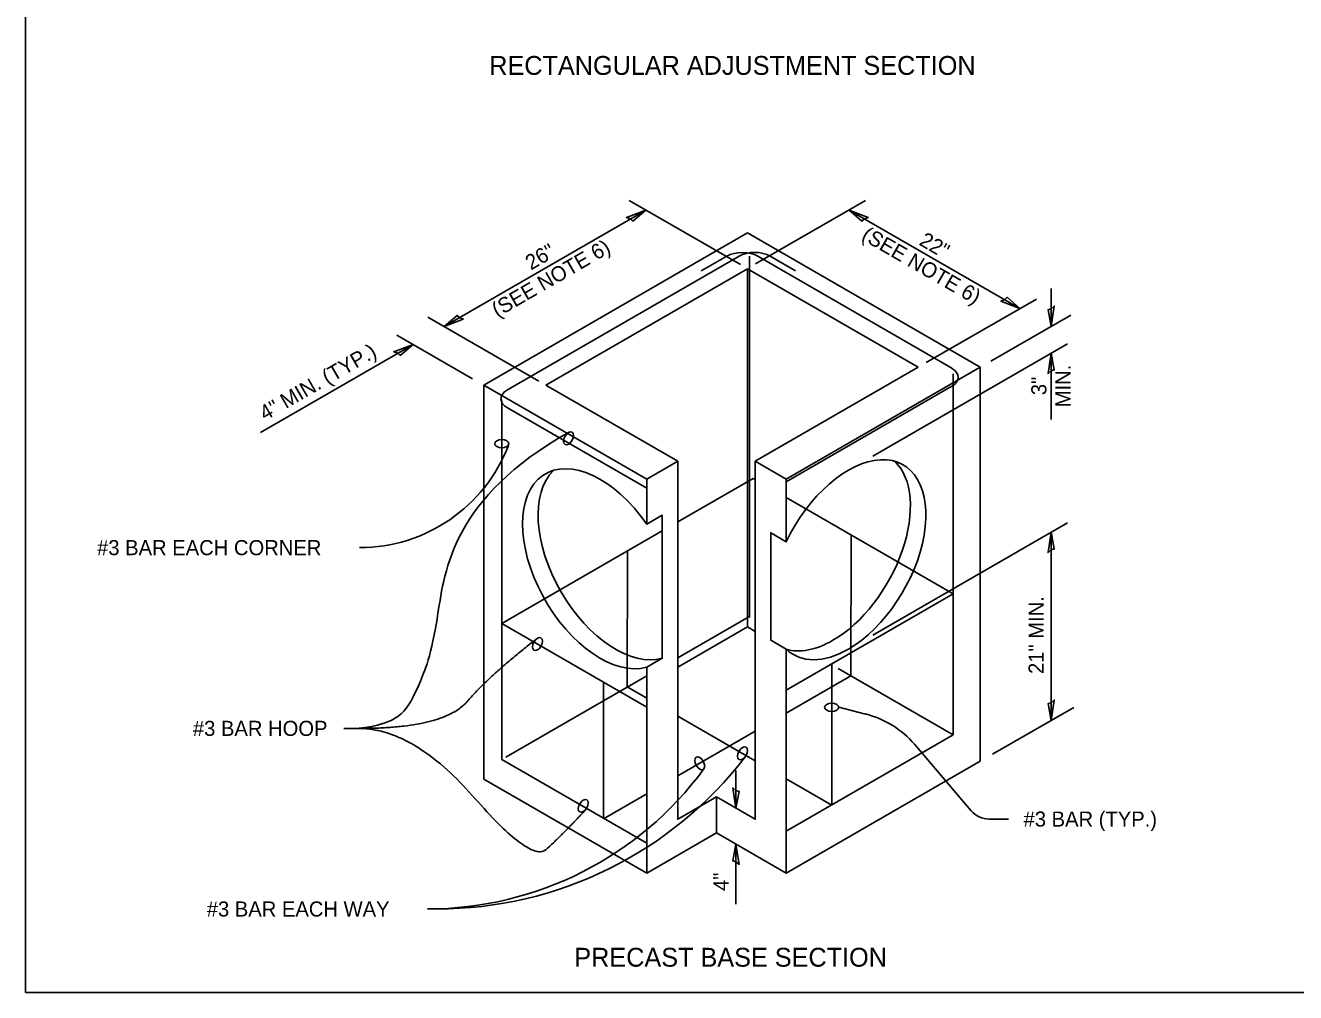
# Model space of a CAD drawing. Extents: x 99862 to 103151, y 100000 to 102076.
# Drawn here: x 99862 to 101209, y 100000 to 101025 of the extents above; entities that cross this region are included whole.
import ezdxf

# ---------------------------------------------------------------- set-up
doc = ezdxf.new("R2010")
doc.units = 0
for name, color, linetype in [('Level 1', 7, 'Continuous'), ('Level 15', 7, 'Continuous'), ('Level 20', 7, 'Continuous'), ('Level 34', 7, 'Continuous'), ('Level 44', 7, 'Continuous'), ('Level 60', 7, 'Continuous'), ('Level 8', 7, 'Continuous')]:
    doc.layers.add(name, color=color, linetype=linetype)

msp = doc.modelspace()

# ---------------------------------------------------------------- linework, layer by layer
at = {"layer": 'Level 1'}
for p, q in [((100348, 100643.8), (100627.6, 100805.3)), ((100627.6, 100805.3), (100874.4, 100662.8)), ((100627.6, 100767.3), (100413.8, 100643.8)), ((100808.5, 100662.8), (100627.6, 100767.3)), ((100627.6, 100767.3), (100627.6, 100387.4)), ((100635.8, 100563.1), (100808.5, 100662.8)), ((100874.4, 100662.8), (100668.7, 100544.1)), ((100874.4, 100662.8), (100874.4, 100244.9)), ((100520.7, 100544.1), (100347.9, 100643.8)), ((100348, 100643.8), (100348, 100225.9)), ((100413.8, 100643.8), (100553.6, 100563.1)), ((100553.6, 100344.6), (100627.6, 100387.4)), ((100635.8, 100382.6), (100627.6, 100387.4)), ((100668.7, 100126.2), (100874.4, 100244.9)), ((100348, 100225.9), (100520.7, 100126.2))]:
    msp.add_line(p, q, dxfattribs=at)
msp.add_lwpolyline([(99862, 99999.5), (103151, 99999.5), (103151, 102075.5), (99862, 102075.5)], close=True, dxfattribs=at)
for centre, major_axis, start_param, end_param in [((100471.3, 100449.1), (-58.1, 100.7), 4.853387, 9.28378), ((100734.5, 100458.7), (58.1, 100.7), 3.926991, 7.995826), ((100718.1, 100468.1), (58.1, 100.7), 3.926991, 6.141613), ((100487.8, 100458.6), (-58.1, 100.7), 0.144003, 3.001512), ((100718.1, 100468.1), (58.1, 100.7), 3.282336, 3.926991), ((100734.5, 100458.7), (58.1, 100.7), 2.999618, 3.926991)]:
    msp.add_ellipse(centre, major_axis=major_axis, ratio=0.57735, start_param=start_param, end_param=end_param, dxfattribs=at)
at = {"layer": 'Level 15'}
for p, q in [((100305.9, 100706.1), (100519.7, 100829.6)), ((100620.1, 100771.7), (100502.2, 100839.6)), ((100636.2, 100772.4), (100752.6, 100839.6)), ((100916.5, 100725.2), (100735.3, 100829.6)), ((100817.2, 100667.8), (100933.9, 100735.2)), ((100949.6, 100706.2), (100949.6, 100746.2)), ((100406.4, 100648.1), (100288.6, 100716)), ((100885.7, 100669.4), (100970.5, 100718.2)), ((100336, 100650.7), (100255.7, 100697)), ((100111.2, 100593.5), (100273, 100687.1)), ((100966.9, 100687.7), (100760.5, 100568.6)), ((100949.6, 100607.3), (100949.6, 100677.7)), ((100966.9, 100497.8), (100760.5, 100378.7)), ((100949.6, 100487.8), (100949.6, 100288.2)), ((100724.4, 100302.1), (100752.6, 100295)), ((100887.4, 100252.3), (100973.5, 100302)), ((100199.5, 100279.8), (100215.5, 100279.8)), ((100864.8, 100192.4), (100804.6, 100262.9)), ((100615.3, 100195.1), (100615.3, 100235.1)), ((100888.3, 100183.6), (100883.8, 100183.6)), ((100888.3, 100183.6), (100904.3, 100183.6)), ((100615.3, 100093.4), (100615.3, 100157)), ((100290.4, 100088.2), (100306.4, 100088.2))]:
    msp.add_line(p, q, dxfattribs=at)
for centre, radius, start, end in [((100216.2, 100640.9), 169.4, 270, 338.8329), ((100728.5, 100198), 100, 40.4774, 76.0603), ((100298.2, 100500), 411.8, 270, 322.5447), ((100288.2, 100451.6), 363.4, 270, 323.7669), ((100883.8, 100208.6), 25, 220.4774, 270)]:
    msp.add_arc(centre, radius, start, end, dxfattribs=at)
for centre, major_axis in [((100437.9, 100587.5), (3.75, 6.5)), ((100367.1, 100581.7), (-7.5, 0)), ((100404.9, 100369.2), (3.75, 6.5)), ((100716.9, 100302.1), (-7.5, 0)), ((100576.9, 100242.8), (-3.75, 6.5)), ((100622.3, 100253.2), (3.75, 6.5)), ((100453.5, 100197.6), (3.75, 6.5))]:
    msp.add_ellipse(centre, major_axis=major_axis, ratio=0.57735, dxfattribs=at)
for points, degree in [([(100438.6, 100594.1), (100314.7, 100524.3), (100298.7, 100370.8), (100279, 100325.8), (100263.6, 100290.9), (100228.2, 100281), (100215.8, 100279.9), (100215.6, 100279.9), (100215.4, 100279.8)], 3), ([(100215.5, 100279.8), (100305.5, 100279.5), (100355, 100336.8), (100403.6, 100374.4)], 2), ([(100215.5, 100279.8), (100274.2, 100279.1), (100398.3, 100136.8), (100430.2, 100165.9), (100456, 100193.5)], 2)]:
    msp.add_open_spline(points, degree=degree, dxfattribs=at)
at = {"layer": 'Level 34'}
for p, q in [((100605.7, 100780.6), (100578.6, 100765)), ((100629.8, 100397.5), (100629.8, 100780.7)), ((100651.5, 100780.7), (100678.6, 100765)), ((100845.7, 100272.9), (100845.7, 100656)), ((100668.7, 100541.3), (100844.4, 100642.8)), ((100367.1, 100246.8), (100367.1, 100627.6)), ((100520.7, 100534.5), (100373.1, 100619.7)), ((100553.6, 100498.8), (100633.5, 100545)), ((100633.5, 100545), (100635.8, 100543.6)), ((100668.7, 100524.6), (100845.7, 100422.4)), ((100367.1, 100391.1), (100537.2, 100489.4)), ((100737.3, 100335.5), (100737.5, 100484.9)), ((100500.1, 100323.7), (100500.2, 100468)), ((100845.7, 100422.4), (100668.7, 100320.2)), ((100553.6, 100354.5), (100628.9, 100398.1)), ((100520.7, 100302.3), (100367.1, 100391.1)), ((100716.9, 100198.5), (100716.9, 100348)), ((100371.4, 100249.3), (100520.7, 100335.5)), ((100668.7, 100295.9), (100737.3, 100335.5)), ((100723.7, 100343.4), (100845.7, 100272.9)), ((100475, 100183.9), (100475, 100328.7)), ((100500.1, 100323.7), (100520.7, 100311.9)), ((100553.6, 100292.9), (100635.8, 100245.3)), ((100553.6, 100229.3), (100635.8, 100276.9)), ((100845.7, 100272.9), (100668.7, 100170.6)), ((100520.7, 100158), (100367.1, 100246.8)), ((100668.7, 100226.3), (100716.9, 100198.5)), ((100475, 100183.9), (100520.7, 100210.3))]:
    msp.add_line(p, q, dxfattribs=at)
for points in [[(100373.1, 100638.9), (100618.6, 100780.7)], [(100844.2, 100661.9), (100638.6, 100780.6)]]:
    msp.add_lwpolyline(points, dxfattribs=at)
for centre, major_axis, start_param, end_param in [((100622.1, 100771.1), (23.3, 0), 0.785398, 2.356194), ((100635.1, 100771.2), (-23.3, 0), 3.926991, 5.497787), ((100827.4, 100652.1), (23.5, 0), 5.497787, 7.068583), ((100389.7, 100629.3), (-23.5, 0), 5.497787, 7.068583)]:
    msp.add_ellipse(centre, major_axis=major_axis, ratio=0.57735, start_param=start_param, end_param=end_param, dxfattribs=at)
at = {"layer": 'Level 44'}
msp.add_lwpolyline([(100520.7, 100496.5), (100520.7, 100496.5), (100520.7, 100496.4), (100537.2, 100505.9), (100537.3, 100354.2), (100537.2, 100354.2), (100520.7, 100344.6), (100520.7, 100126.2), (100594.7, 100168.9), (100594.7, 100207), (100553.6, 100183.3), (100553.6, 100344.6), (100553.6, 100563.1), (100520.7, 100544.1), (100520.7, 100496.5)], dxfattribs=at)
msp.add_lwpolyline([(100635.8, 100371.4), (100635.8, 100183.3), (100594.7, 100207), (100594.7, 100168.9), (100668.7, 100126.2), (100668.7, 100363.7), (100652.3, 100373.2), (100652.3, 100487.2), (100668.7, 100477.7), (100668.7, 100544.1), (100635.8, 100563.1)], close=True, dxfattribs=at)
msp.add_ellipse((100471.3, 100449.1), major_axis=(-58.1, 100.7), ratio=0.57735, start_param=4.853387, end_param=4.853404, dxfattribs=at)
at = {"layer": 'Level 60'}
msp.add_line((99862, 99999.5), (99862, 99999.5), dxfattribs=at)
msp.add_line((99862, 99999.5), (99862, 99999.5), dxfattribs=at)
msp.add_line((99862, 99999.5), (99862, 99999.5), dxfattribs=at)
at = {"layer": 'Level 8'}
for points in [[(100519.7, 100829.6), (100499.3, 100821.7), (100503.4, 100820.2), (100506, 100817.9)], [(100735.3, 100829.6), (100748.9, 100817.9), (100751.5, 100820.3), (100755.6, 100821.7)], [(100916.5, 100725.2), (100902.9, 100737), (100900.3, 100734.6), (100896.2, 100733.1)], [(100949.6, 100706.2), (100952.9, 100727.8), (100949.6, 100724.9), (100946.3, 100723.9)], [(100305.9, 100706.1), (100326.3, 100714), (100322.2, 100715.5), (100319.6, 100717.9)], [(100273, 100687.1), (100252.6, 100679.2), (100256.8, 100677.7), (100259.3, 100675.3)], [(100949.6, 100677.7), (100952.9, 100660), (100949.6, 100659), (100946.3, 100656.1)], [(100949.6, 100487.8), (100952.9, 100470.1), (100949.6, 100469.1), (100946.3, 100466.2)], [(100949.6, 100288.2), (100952.9, 100309.8), (100949.6, 100307), (100946.3, 100306)], [(100615.3, 100195.1), (100618.6, 100212.9), (100615.3, 100213.9), (100611.9, 100216.7)], [(100615.3, 100157), (100618.6, 100135.4), (100615.3, 100138.3), (100611.9, 100139.3)]]:
    msp.add_lwpolyline(points, close=True, dxfattribs=at)

# ---------------------------------------------------------------- texts
at = {"layer": 'Level 20'}
for s, height, p in [('RECTANGULAR ADJUSTMENT SECTION', 20, (100353.8, 100973)), ('#3 BAR EACH CORNER', 16, (99938, 100463.5)), ('#3 BAR HOOP', 16, (100039.6, 100271.8)), ('#3 BAR (TYP.)', 16, (100920.3, 100175.6)), ('#3 BAR EACH WAY', 16, (100054.3, 100080.2)), ('PRECAST BASE SECTION', 20, (100444, 100027))]:
    msp.add_text(s, height=height, dxfattribs=at).set_placement(p)
for s, rotation, p in [('(SEE NOTE 6)', 330.0271, (100747.4, 100799)), ('22"', 330.0271, (100808.5, 100793.2)), ('(SEE NOTE 6)', 29.9987, (100362.4, 100715.3)), ('26"', 29.9987, (100398, 100765.4)), ('4" MIN. (TYP.)', 29.9987, (100116.1, 100605.7)), ('MIN.', 90, (100970.1, 100620.4)), ('3"', 90, (100944.5, 100633.2)), ('21" MIN.', 90, (100941.6, 100337.5)), ('4"', 90.0001, (100607.5, 100107.3))]:
    msp.add_text(s, height=16, rotation=rotation, dxfattribs=at).set_placement(p)

doc.saveas('drawing.dxf')
